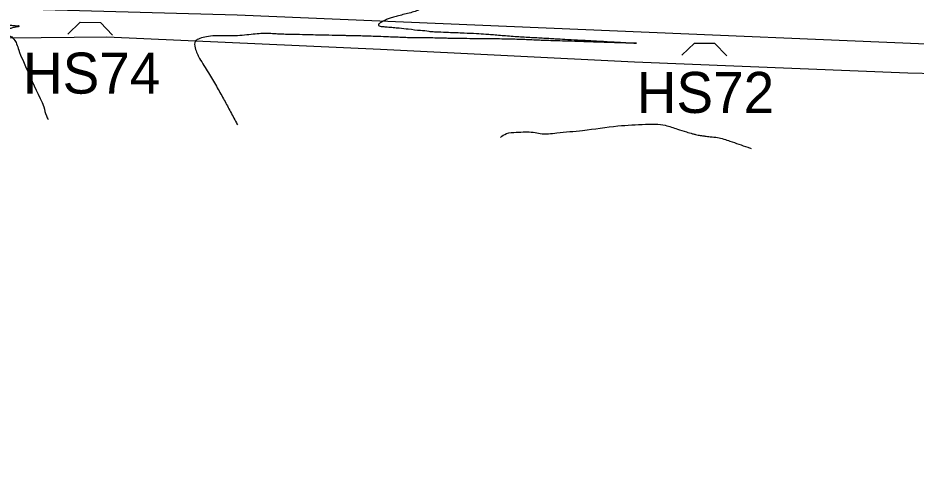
# Model space of a CAD drawing. Extents: x -478495 to -472450, y -1118050 to -1113745.
# Drawn here: x -477644.2 to -477425.6, y -1117514.1 to -1117404.2 of the extents above; entities that cross this region are included whole.
import ezdxf

# ---------------------------------------------------------------- set-up
doc = ezdxf.new("R2010")
doc.units = 0
for name, color, linetype in [('hospodářské sjezdy', 7, 'Continuous'), ('hranice kú', 7, 'Continuous'), ('ObPÚ', 7, 'Continuous'), ('silnice', 7, 'Continuous'), ('Vrstevnice_vedlejsi', 7, 'Continuous')]:
    doc.layers.add(name, color=color, linetype=linetype)

msp = doc.modelspace()

# ---------------------------------------------------------------- linework, layer by layer
at = {"layer": 'hospodářské sjezdy'}
for p, q in [((-477632.07, -1117408.15), (-477629, -1117405.19)), ((-477629, -1117405.19), (-477624.12, -1117405.27)), ((-477624.12, -1117405.27), (-477621.15, -1117408.34)), ((-477482.55, -1117413.27), (-477479.5, -1117410.28)), ((-477479.5, -1117410.28), (-477474.62, -1117410.33)), ((-477474.62, -1117410.33), (-477471.63, -1117413.37))]:
    msp.add_line(p, q, dxfattribs=at)
at = {"layer": 'hranice kú'}
for p, q in [((-477646.48, -1117409.04), (-477622.53, -1117408.79)), ((-477622.53, -1117408.79), (-477555.97, -1117411.81)), ((-477555.97, -1117411.81), (-477494.12, -1117414.84)), ((-477494.12, -1117414.84), (-477427.56, -1117417.53)), ((-477427.56, -1117417.53), (-477374.08, -1117418.87))]:
    msp.add_line(p, q, dxfattribs=at)
at = {"layer": 'ObPÚ'}
for p, q in [((-477646.48, -1117409.04), (-477622.53, -1117408.79)), ((-477622.53, -1117408.79), (-477555.97, -1117411.81)), ((-477555.97, -1117411.81), (-477494.12, -1117414.84)), ((-477494.12, -1117414.84), (-477427.56, -1117417.53)), ((-477427.56, -1117417.53), (-477374.08, -1117418.87))]:
    msp.add_line(p, q, dxfattribs=at)
at = {"layer": 'silnice'}
msp.add_lwpolyline([(-478070.5, -1117514.11), (-478065.52, -1117512.47), (-477835.7, -1117440.29), (-477736.73, -1117410.08), (-477702.34, -1117405.05), (-477652.85, -1117401.69), (-477590.78, -1117403.37), (-477332.45, -1117414.28), (-477204.96, -1117416.8), (-477142.05, -1117416.8), (-477096.76, -1117410.08), (-477037.2, -1117399.17), (-476978.49, -1117379.03), (-476883.71, -1117344.63), (-476756.22, -1117298.47), (-476633.76, -1117254.83), (-476588.47, -1117242.24), (-476550.73, -1117234.69), (-476503.76, -1117230.5), (-476424.07, -1117228.82)], dxfattribs=at)
at = {"layer": 'Vrstevnice_vedlejsi'}
for points in [[(-477508.03, -1117400.64), (-477507.1, -1117400.77), (-477506.86, -1117400.88), (-477507.3, -1117400.97), (-477508.43, -1117401.05), (-477509.25, -1117401.1), (-477509.76, -1117401.11), (-477509.95, -1117401.09), (-477510.25, -1117401.07), (-477510.66, -1117401.05), (-477511.16, -1117401.04), (-477512.3, -1117400.97), (-477514.07, -1117400.86), (-477516.48, -1117400.71), (-477518.17, -1117400.6), (-477519.16, -1117400.54), (-477519.45, -1117400.54), (-477519.78, -1117400.53), (-477520.16, -1117400.52), (-477520.59, -1117400.51), (-477521.58, -1117400.5), (-477523.11, -1117400.49), (-477525.21, -1117400.48), (-477527.07, -1117400.47), (-477528.72, -1117400.47), (-477530.14, -1117400.47), (-477531.41, -1117400.47), (-477532.52, -1117400.48), (-477533.48, -1117400.49), (-477534.68, -1117400.48), (-477536.11, -1117400.44), (-477537.78, -1117400.38), (-477539.03, -1117400.34), (-477539.84, -1117400.33), (-477540.22, -1117400.33), (-477540.44, -1117400.4), (-477540.49, -1117400.52), (-477540.37, -1117400.7), (-477540.71, -1117400.83), (-477541.51, -1117400.93), (-477542.76, -1117400.98), (-477543.97, -1117401.19), (-477545.13, -1117401.55), (-477546.25, -1117402.07), (-477547.52, -1117402.55), (-477548.93, -1117402.98), (-477550.49, -1117403.36), (-477551.86, -1117403.73), (-477553.05, -1117404.08), (-477554.06, -1117404.41), (-477554.94, -1117404.77), (-477555.7, -1117405.18), (-477556.33, -1117405.63), (-477556.44, -1117405.97), (-477556.04, -1117406.18), (-477555.12, -1117406.28), (-477554.28, -1117406.36), (-477553.51, -1117406.42), (-477552.82, -1117406.47), (-477551.37, -1117406.61), (-477549.16, -1117406.84), (-477546.18, -1117407.17), (-477544.19, -1117407.38), (-477543.18, -1117407.49), (-477543.16, -1117407.49), (-477543.14, -1117407.5), (-477543.13, -1117407.5), (-477543.12, -1117407.5), (-477541.86, -1117407.55), (-477539.35, -1117407.65), (-477535.59, -1117407.8), (-477532.58, -1117407.94), (-477530.31, -1117408.08), (-477528.8, -1117408.2), (-477527.18, -1117408.33), (-477525.47, -1117408.47), (-477523.64, -1117408.61), (-477521.84, -1117408.74), (-477520.05, -1117408.85), (-477518.28, -1117408.94), (-477516.58, -1117409.03), (-477514.95, -1117409.12), (-477513.38, -1117409.22), (-477511.07, -1117409.34), (-477508.02, -1117409.51), (-477504.23, -1117409.72), (-477500.73, -1117409.91), (-477497.53, -1117410.09), (-477494.61, -1117410.26), (-477493.63, -1117410.33), (-477494.59, -1117410.33), (-477497.48, -1117410.24), (-477500.65, -1117410.14), (-477504.11, -1117410.03), (-477507.87, -1117409.91), (-477511, -1117409.81), (-477513.51, -1117409.73)], [(-477670.6, -1117405.07), (-477670.42, -1117405.05), (-477669.57, -1117405.01), (-477668.05, -1117404.93), (-477665.87, -1117404.82), (-477664.26, -1117404.74), (-477663.23, -1117404.69), (-477662.77, -1117404.66), (-477662.35, -1117404.67), (-477661.97, -1117404.71), (-477661.63, -1117404.77), (-477660.87, -1117404.86), (-477659.69, -1117404.97), (-477658.09, -1117405.1), (-477657.02, -1117405.19), (-477656.49, -1117405.24), (-477656.48, -1117405.24), (-477656.3, -1117405.28), (-477655.94, -1117405.38), (-477655.4, -1117405.52), (-477654.63, -1117405.63), (-477653.63, -1117405.73), (-477652.4, -1117405.8), (-477651.08, -1117405.85), (-477649.66, -1117405.88), (-477648.14, -1117405.89), (-477646.93, -1117405.91), (-477646.04, -1117405.94), (-477645.46, -1117405.97), (-477644.93, -1117406.01), (-477644.43, -1117406.06), (-477643.98, -1117406.11), (-477643.98, -1117406.21), (-477644.41, -1117406.35), (-477645.29, -1117406.53), (-477646.17, -1117406.76), (-477647.05, -1117407.04), (-477647.94, -1117407.38), (-477648.4, -1117407.65), (-477648.42, -1117407.85), (-477648.01, -1117408), (-477647.46, -1117408.18), (-477646.75, -1117408.41), (-477645.89, -1117408.67), (-477645.15, -1117409.36), (-477644.51, -1117410.47), (-477643.99, -1117412), (-477643.02, -1117414.39), (-477641.6, -1117417.63), (-477637.84, -1117425.82)], [(-477513.51, -1117409.73), (-477515.41, -1117409.67), (-477517.25, -1117409.6), (-477519.06, -1117409.52), (-477520.82, -1117409.45), (-477522.72, -1117409.38), (-477524.77, -1117409.33), (-477526.97, -1117409.29), (-477529.39, -1117409.26), (-477532.03, -1117409.23), (-477534.91, -1117409.21), (-477537.29, -1117409.19), (-477539.17, -1117409.15), (-477540.56, -1117409.1), (-477542.23, -1117409.06), (-477544.18, -1117409.03), (-477546.41, -1117409.02), (-477548.26, -1117408.99), (-477549.74, -1117408.96), (-477550.84, -1117408.92), (-477552.44, -1117408.85), (-477554.53, -1117408.77), (-477557.12, -1117408.67), (-477559.35, -1117408.59), (-477561.2, -1117408.54), (-477562.69, -1117408.51), (-477563.95, -1117408.49), (-477564.99, -1117408.47), (-477565.79, -1117408.46), (-477567.72, -1117408.41), (-477570.75, -1117408.35), (-477574.89, -1117408.25), (-477577.8, -1117408.19), (-477579.49, -1117408.15), (-477579.94, -1117408.13), (-477580.73, -1117408.09), (-477581.86, -1117408.03), (-477583.34, -1117407.96), (-477585.02, -1117407.99), (-477586.91, -1117408.12), (-477589.01, -1117408.36), (-477591.26, -1117408.51), (-477593.67, -1117408.56), (-477596.23, -1117408.53), (-477598.31, -1117408.73), (-477599.9, -1117409.17), (-477601.01, -1117409.84), (-477601.03, -1117411.46), (-477599.96, -1117414.02), (-477597.81, -1117417.53), (-477595.87, -1117420.81), (-477594.14, -1117423.86), (-477592.63, -1117426.68), (-477591.02, -1117429.73), (-477590.74, -1117430.25)], [(-477637.84, -1117425.82), (-477637.26, -1117428.02), (-477636.82, -1117428.94)], [(-477526.75, -1117433.27), (-477525.28, -1117432.36), (-477522.87, -1117432.04), (-477520.7, -1117431.94), (-477518.75, -1117432.04), (-477517.04, -1117432.35), (-477513.03, -1117432.19), (-477506.73, -1117431.57), (-477498.14, -1117430.49), (-477491.43, -1117430.08), (-477486.61, -1117430.33), (-477483.67, -1117431.25), (-477481.46, -1117431.93), (-477479.98, -1117432.37), (-477479.23, -1117432.56), (-477478.62, -1117432.7), (-477478.14, -1117432.8), (-477477.79, -1117432.85), (-477476.98, -1117432.96), (-477475.68, -1117433.11), (-477473.91, -1117433.32), (-477470.87, -1117434.18), (-477466.56, -1117435.68), (-477465.7, -1117436)]]:
    msp.add_spline(points, degree=3, dxfattribs=at)

# ---------------------------------------------------------------- texts
at = {"layer": 'hospodářské sjezdy'}
for s, p in [('HS74', (-477642.95, -1117422.61)), ('HS72', (-477493.56, -1117427.32))]:
    msp.add_text(s, height=10, rotation=360, dxfattribs=at).set_placement(p)

doc.saveas('drawing.dxf')
